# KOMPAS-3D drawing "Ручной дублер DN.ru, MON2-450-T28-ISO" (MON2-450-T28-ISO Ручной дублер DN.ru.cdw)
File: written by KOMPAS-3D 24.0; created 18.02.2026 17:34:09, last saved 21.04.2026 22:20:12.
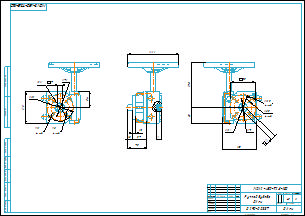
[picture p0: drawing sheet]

Document properties: Автор: R2D2; Форматы листов документа: A2; Полное имя файла: MON2-450-T28-ISO Ручной дублер DN.ru.m3d; Масса: 4.5; Наименование: Ручной дублер DN.ru; Количество листов документа: 1; Примечание: D290-00337

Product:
- Body: Тело 4  | qty 1
    Масса: 12.336453
- Part/product: Ручной дублер DN.ru  | designation MON2-450-T28-ISO
    Масса: 4.5
    Раздел спецификации: Прочие изделия
    Форматы листов документа: A2
    Примечание: D290-00337

Views: Вид 1, Спереди, Проекционный вид 2, Местный разрез 1, Проекционный вид 3
Referenced files in E:\Работа\Зайцев\Аксессуары для пневмоприводов\Ручной дублер DN.ru\MON2-450-T28-ISO Ручной дублер DN.ru\: MON2-450-T28-ISO Ручной дублер DN.ru.m3d
Referenced files in E:\Работа\Зайцев\Для компаса\: чертеж DN.ru А3.cdt
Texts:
  MON2-450-T28-ISO
  чертеж DN.ru А3.cdt
  Ручной дублер
  Ручной дублер DN.ru
  MON2-450-T28-ISO Ручной дублер DN.ru
Dimensions and other numbers on the sheet: 0; 3; 2; 4; 64; 125; 110; 10; 4 отв.; 8; 70; 102; 17; 18; 75; 22; 13; 57; 200; 5; 178; 63; 95; 135; 10,5; 8,5; 1:2; 1; 4,5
